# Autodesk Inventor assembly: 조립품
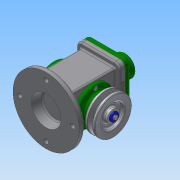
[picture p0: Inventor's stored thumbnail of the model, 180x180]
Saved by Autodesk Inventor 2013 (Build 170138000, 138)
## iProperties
Created: 2018-10
Part Number: 조립품
Document SubType Name: Assembly
Designer: Administrator
Author: Administrator
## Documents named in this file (18)
- C:\Users\Administrator\Desktop\481007V1060\481007V1060\조립품.iam
- C:\Users\Administrator\Desktop\481007V1060\481007V1060\E-링.ipt
- C:\Users\Administrator\Desktop\481007V1060\481007V1060\V-벨트풀리.ipt
- C:\Users\Administrator\Desktop\481007V1060\481007V1060\덮개.ipt
- C:\Users\Administrator\Desktop\481007V1060\481007V1060\뒤커버.ipt
- C:\Users\Administrator\Desktop\481007V1060\481007V1060\링크.ipt
- C:\Users\Administrator\Desktop\481007V1060\481007V1060\베어링 17 x 40 x 12.ipt
- C:\Users\Administrator\Desktop\481007V1060\481007V1060\본체.ipt
- C:\Users\Administrator\Desktop\481007V1060\481007V1060\볼트 M4 x 8.ipt
- C:\Users\Administrator\Desktop\481007V1060\481007V1060\볼트 M4 x 10.ipt
- C:\Users\Administrator\Desktop\481007V1060\481007V1060\슬라이더.ipt
- C:\Users\Administrator\Desktop\481007V1060\481007V1060\앞커버.ipt
- C:\Users\Administrator\Desktop\481007V1060\481007V1060\오일 실 17 30 8.ipt
- C:\Users\Administrator\Desktop\481007V1060\481007V1060\와셔 4x16.ipt
- C:\Users\Administrator\Desktop\481007V1060\481007V1060\클레비스 핀 6 x 22.ipt
- 클레비스 핀 6 x 22.ipt
- C:\Users\Administrator\Desktop\481007V1060\481007V1060\키 4 x 4 x 12.ipt
- C:\Users\Administrator\Desktop\481007V1060\481007V1060\편심축.ipt
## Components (2 placed, 2 different names)
1. E-링:1
2. V-벨트풀리:1
